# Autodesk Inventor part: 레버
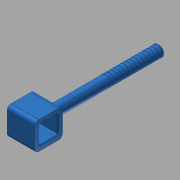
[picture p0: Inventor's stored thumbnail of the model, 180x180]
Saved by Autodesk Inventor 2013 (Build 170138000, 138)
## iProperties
Created: 2015-12
Part Number: 레버
Material: 스테인리스강
Document SubType Name: Modeling
Designer: mduedu
Density: 8.08 g/cm^3
Mass: 28.4605 g
Surface Area: 28.1796 cm^2
Volume: 3.52234 cm^3
Author: mduedu
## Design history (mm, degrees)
sketch "스케치1"
  geometry: C1 r 3 at (0, 0); 1 further point
  constraints: 1 centre point, 1 coincident
  dimensions: "d0" = 6 diameter of C1
extrude "돌출1" new body sketch "스케치1" distance "d1" = 60; taper "d2" = 0 deg
sketch "스케치5"
  geometry: L1 (-7.5, -7.5)-(7.5, -7.5); L2 (7.5, -7.5)-(7.5, 7.5); L3 (7.5, 7.5)-(-7.5, 7.5); L4 (-7.5, 7.5)-(-7.5, -7.5); L5 (-7.5, -7.5)-(7.5, 7.5); L6 (7.5, -7.5)-(-7.5, 7.5); C1 r 3 at (0, 0) reference
  constraints: 12 end point, 2 midpoint, 2 parallel, 2 perpendicular, 1 horizontal
  dimensions: "d24" = 15 distance of L2.end L3.end
extrude "돌출2" join sketch "스케치5" distance "d26" = 15; taper "d27" = 0 deg
chamfer "모따기1" distance "d7" = 0.5; stored, may be unused: second distance "d8" = 2, angle "d9" = 45 deg
fillet "모깎기2" dims "d11" = 1
sketch "스케치4"
  geometry: L1 (-60, -2.5)-(-60, 2.5) reference; L2 (-60, 0)-(0, 0); L3 (-1, 3)-(-59.5, 3) reference; L4 (-59, 3)-(-58.9, 3); L5 (-58.9, 3)-(-58.9, 2.9); L6 (-58.9, 2.9)-(-59, 2.9); L7 (-59, 2.9)-(-59, 3)
  constraints: 10 end point, 2 parallel, 2 perpendicular, 1 horizontal, 1 midpoint, 1 point on line
  dimensions: "d17" = 1 distance between parallel lines of L7 L1; "d18" = 0.1 distance of L5.end L6.end; "d19" = 0.1 distance of L4.end L5.end
revolve "회전3" sketch "스케치4" stored, may be unused: angle "d20" = 90 deg
sketch "스케치6"
  geometry: L1 (0, 0)-(15, 0) reference; L2 (15, 15)-(15, 0) reference; L3 (0, 15)-(15, 15) reference; L4 (7.5, 15)-(7.5, 0); L5 (0, 7.5)-(15, 7.5); L6 (2.5, 2.5)-(12.5, 2.5); L7 (12.5, 2.5)-(12.5, 12.5); L8 (12.5, 12.5)-(2.5, 12.5); L9 (2.5, 12.5)-(2.5, 2.5); L10 (2.5, 2.5)-(12.5, 12.5); L11 (12.5, 2.5)-(2.5, 12.5); 1 further point
  constraints: 16 end point, 6 midpoint, 2 parallel, 2 perpendicular, 1 horizontal
  dimensions: "d29" = 10 distance of L7.end L8.end; "d31" = 2.5 distance between parallel lines of L8 L3 (derived)
extrude "돌출3" cut sketch "스케치6" stored distance "d32" = 15; taper "d33" = 0 deg
fillet "모깎기3" dims "d34" = 2, "d35" = 1
chamfer "모따기2" distance "d36" = 0.5; stored, may be unused: second distance "d37" = 2, angle "d38" = 45 deg
node "솔리드1"
pattern_linear "직사각형 패턴1" dims "d23" = 2
